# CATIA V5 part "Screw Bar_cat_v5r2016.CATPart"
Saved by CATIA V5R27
Part number: Screw Bar
Bounding box of the stored display mesh (mm): x -3 to 3, y -52 to 52, z -3 to 3
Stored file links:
  E:\_Deepak\2017_Deepak\CATIA\Resources\Tutorial Files\Tutorials\c13_catia_v5_6r2016_tut\c13tut2\c13tut02.CATParts\Screw Bar_cat_v5r2016.CATPart
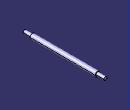
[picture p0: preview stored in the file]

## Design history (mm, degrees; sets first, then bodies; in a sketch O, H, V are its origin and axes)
Body1 (main body)
  Sketch1 on zx-plane, origin (0, 0, 0), H (-1, 0, 0), V (0, 0, 1)
    circle A1 centre (0, 0) radius 2
    radius A1 = 2
  Sketch2 on zx-plane, origin (0, 0, 0), H (-1, 0, 0), V (0, 0, 1)
    circle A1 centre (0, 0) radius 3
    radius A1 = 3
  Pad1: profile Sketch1, direction (0, 1, 0), length 52, mirrored extent
  Pad2: profile Sketch2, direction (0, 1, 0), length 42, mirrored extent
